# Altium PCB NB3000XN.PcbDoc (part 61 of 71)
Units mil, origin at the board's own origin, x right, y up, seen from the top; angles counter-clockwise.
Board outline 9527.56 x 6929.77 mil, 6 copper layers (Top Layer, GND+SHIELD, MidLayer1, MidLayer2, P2 - 3V3+5V0, Bottom Layer), stack 62.375 mil thick; 832 components, 1027 nets, 4655 pads, 4981 vias.
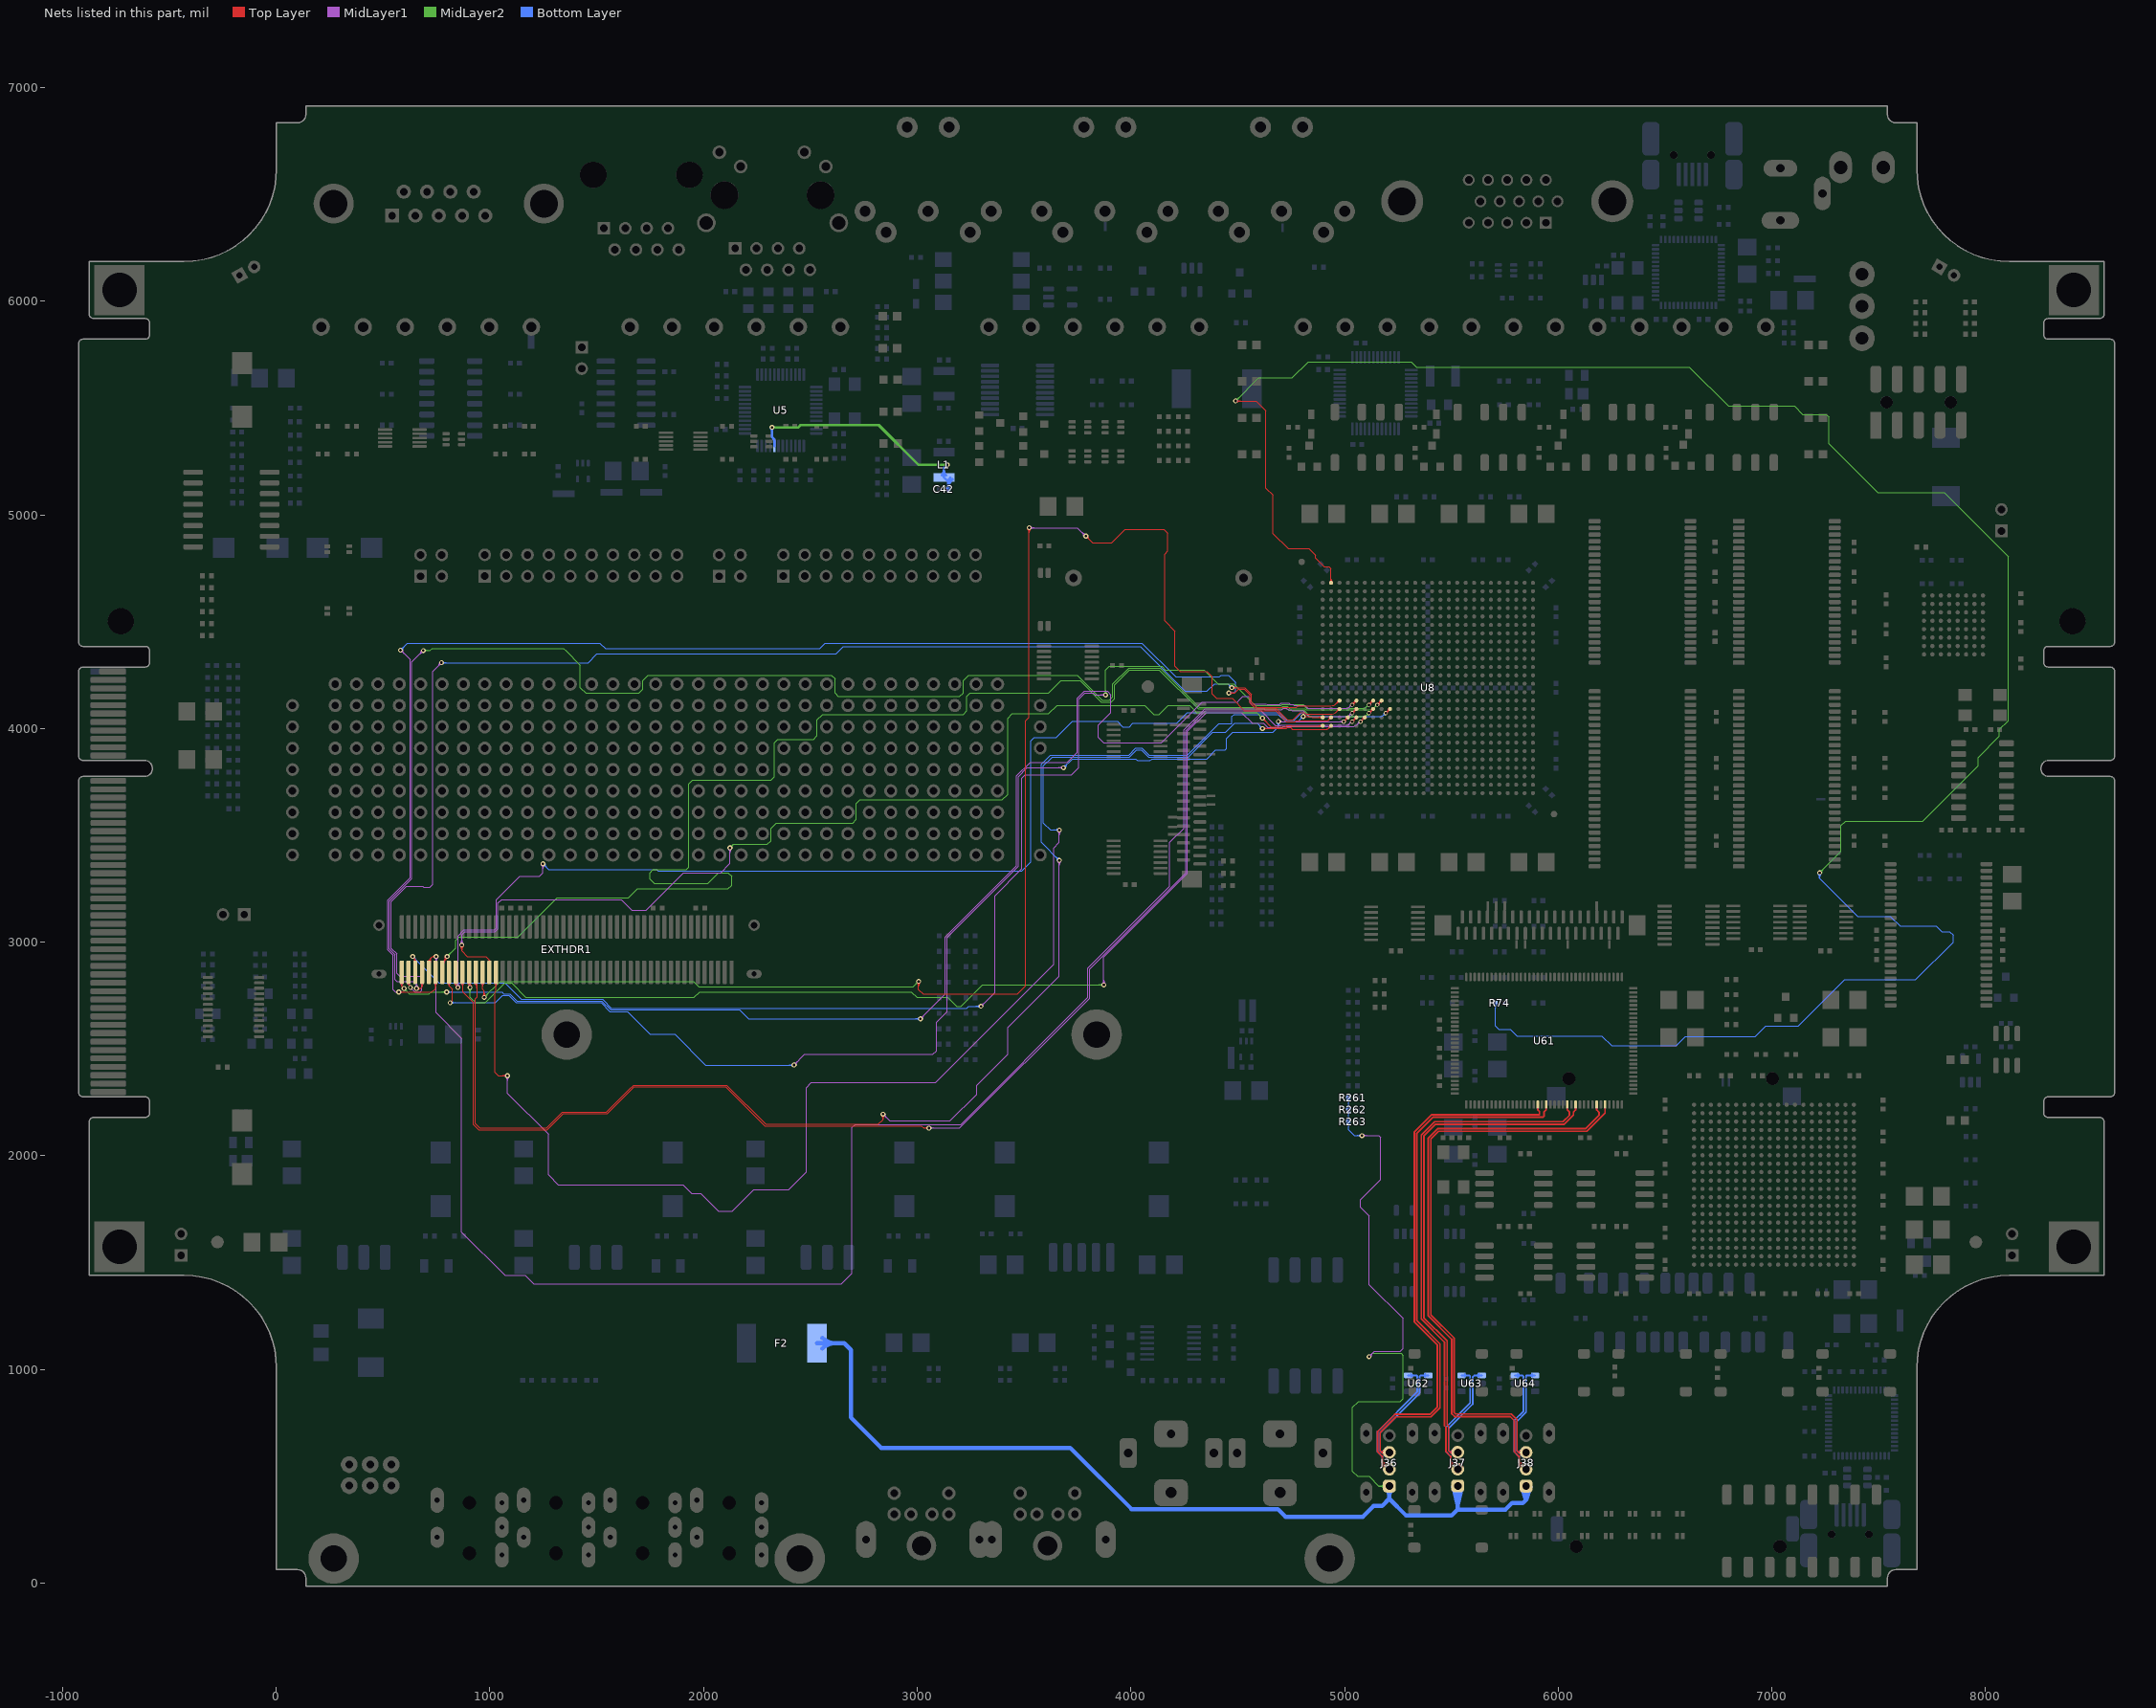
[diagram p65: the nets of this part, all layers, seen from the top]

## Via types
v1: diameter 23, hole 11.81, Top Layer to Bottom Layer, 3672 vias
v2: diameter 26, hole 11.81, Top Layer to Bottom Layer, 461 vias
v3: diameter 19, hole 11.81, Top Layer to Bottom Layer, tented both sides, 396 vias
v4: diameter 23.62, hole 11.81, Top Layer to Bottom Layer, 288 vias
v5: diameter 20, hole 11.81, Top Layer to Bottom Layer, 91 vias
v6: diameter 23, hole 11.81, Top Layer to Bottom Layer, tented both sides, 50 vias
v7: diameter 31, hole 11.81, Top Layer to Bottom Layer, 15 vias
v8: diameter 27.56, hole 11.81, Top Layer to Bottom Layer, tented both sides, 4 vias
v9: diameter 29, hole 11.81, Top Layer to Bottom Layer, 3 vias
v10: diameter 21, hole 11.81, Top Layer to Bottom Layer, 1 vias

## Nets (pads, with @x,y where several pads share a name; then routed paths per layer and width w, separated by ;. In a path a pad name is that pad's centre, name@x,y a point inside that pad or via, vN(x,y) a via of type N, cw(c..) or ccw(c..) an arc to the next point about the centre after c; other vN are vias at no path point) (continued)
PBIO.D35: EXTHDR1.72 U8.V2 | length 7156.9
  Top Layer w4: EXTHDR1.72@1023.3,2808.48 cw(c1009.65,2794.82) 1028.96,2794.82 cw(c1048.27,2794.82) EXTHDR1.72@1034.62,2808.48 ; EXTHDR1.72@1028.96,2814.13 EXTHDR1.72@1028.96,2859.25 1028.96,2770.43 1023.52,2765 1023.52,2391.71 1040.19,2375.04 v1(1081.86,2375.04) ; v1@1075.14,2368.32 ccw(c1058.92,2352.11) 1058.92,2375.04 ccw(c1058.92,2397.98) v1@1075.14,2381.76 ; v1@1077.97,2371.15 ccw(c1068.58,2361.76) 1068.58,2375.04 ccw(c1068.58,2388.32) v1@1077.97,2378.93 ; v1(4616.19,4000.04) 4727.77,4000.04 4732.94,4005.21 4747.44,4005.21 ; v1@4620.08,3996.15 cw(c4629.47,3986.76) 4629.47,4000.04 cw(c4629.47,4013.32) v1@4620.08,4003.93 ; v1@4622.91,3993.32 cw(c4639.13,3977.11) 4639.13,4000.04 cw(c4639.13,4022.98) v1@4622.91,4006.76 ; 4752.65,4000 4747.44,4005.21 ; U8.V2@4929.9,4012.83 cw(c4912.17,4012.83) 4924.71,4000.3 ; U8.V2@4937.24,4005.49 ccw(c4937.24,3987.77) 4924.71,4000.3 ; 4747.44,4005.21 4755.32,3997.33 4860,3997.33 4870,3997.33 4917.53,3997.33 ccw(c4917.53,4007.48) 4924.71,4000.3
  MidLayer1 w4: v1@1075.14,2368.32 cw(c1058.92,2352.11) 1081.86,2352.11 cw(c1104.79,2352.11) v1@1088.57,2368.32 ; v1@1077.97,2371.15 cw(c1068.58,2361.76) 1081.86,2361.76 cw(c1095.14,2361.76) v1@1085.75,2371.15 ; v1(1081.86,2375.04) 1081.86,2293.14 1273.86,2101.14 1273.86,1911.14 1320,1865 1905,1865 1945,1825 1986.71,1825 2070,1741.71 2135,1741.71 2235.29,1842 2398.82,1842 2481.86,1925.04 2481.86,2319.23 2505.13,2342.5 3085.63,2342.5 3108.73,2365.6 ; 3090.98,2347.85 3640,2896.87 3640,3441.52 3665.19,3466.71 v1(3665.19,3525.04) ; v1@3658.47,3518.32 cw(c3642.26,3502.11) 3665.19,3502.11 cw(c3688.13,3502.11) v1@3671.91,3518.32 ; v1@3661.3,3521.15 cw(c3651.91,3511.76) 3665.19,3511.76 cw(c3678.47,3511.76) v1@3669.08,3521.15
  Bottom Layer w4: v1@3658.47,3518.32 ccw(c3642.26,3502.11) 3642.26,3525.04 ccw(c3642.26,3547.98) v1@3658.47,3531.76 ; v1@3661.3,3521.15 ccw(c3651.91,3511.76) 3651.91,3525.04 ccw(c3651.91,3538.32) v1@3661.3,3528.93 ; v1(3665.19,3525.04) 3623.52,3525.04 3590.19,3558.37 3590.19,3825.04 3631.86,3866.71 3993.17,3866.71 4026.5,3900.04 4049.52,3900.04 4082.86,3866.71 4268.17,3866.71 4383.84,3982.37 4410,3982.37 4443.19,3982.37 4485.86,4025.04 4591.19,4025.04 v1(4616.19,4000.04) ; v1@4606.69,4000.04 ccw(c4583.76,4000.04) 4599.97,4016.26 ccw(c4616.19,4032.48) v1@4616.19,4009.54 ; v1@4610.69,4000.04 ccw(c4597.41,4000.04) 4606.8,4009.43 ccw(c4616.19,4018.82) v1@4616.19,4005.54
PBIO.D36: EXTHDR1.74 U8.V1 | length 5688.9
  Top Layer w4: v1@861.81,2979.99 cw(c845.59,2963.77) 868.52,2963.77 cw(c891.46,2963.77) v1@875.24,2979.99 ; v1@864.64,2982.82 cw(c855.25,2973.43) 868.52,2973.43 cw(c881.8,2973.43) v1@872.41,2982.82 ; v1(868.52,2986.71) 868.52,2958.37 893.52,2933.37 981.86,2933.37 997.46,2917.77 ; EXTHDR1.74@993.67,2911.41 ccw(c990.24,2917.77) 997.46,2917.77 ; EXTHDR1.74@997.46,2859.25 997.46,2917.77 ; EXTHDR1.74@1001.26,2911.41 cw(c1004.69,2917.77) 997.46,2917.77 ; v1@4616.19,4039.54 cw(c4616.19,4016.61) 4632.41,4032.82 cw(c4648.63,4049.04) v1@4625.69,4049.04 ; v1@4616.19,4043.54 cw(c4616.19,4030.26) 4625.58,4039.65 cw(c4634.97,4049.04) v1@4621.69,4049.04 ; v1(4616.19,4049.04) 4656.86,4008.37 4724.79,4008.37 4729.63,4013.21 4750.75,4013.21 4751.13,4012.83 4860,4012.83 4870,4012.83 U8.V1@4897.87,4012.83 ; U8.V1@4892.57,4007.53 ccw(c4879.77,3994.73) 4879.77,4012.83 ccw(c4879.77,4030.94) U8.V1@4892.57,4018.14 ; U8.V1@4892.68,4007.64 ccw(c4880.15,3995.11) 4880.15,4012.83 ccw(c4880.15,4030.56) U8.V1@4892.68,4018.03
  MidLayer1 w4: v1@861.81,2993.43 ccw(c845.59,3009.64) 868.52,3009.64 ccw(c891.46,3009.64) v1@875.24,2993.43 ; v1@864.64,2990.6 ccw(c855.25,2999.99) 868.52,2999.99 ccw(c881.8,2999.99) v1@872.41,2990.6 ; v1(868.52,2986.71) 868.52,3035.9 882.34,3049.71 1024.71,3049.71 1038,3063 1038,3183 1055.04,3200.04 1615.19,3200.04 1665.19,3150.04 1731.86,3150.04 1906.82,3325 2080,3325 2123.52,3368.52 v1(2123.52,3441.71) ; v1@2116.81,3434.99 cw(c2100.59,3418.77) 2123.52,3418.77 cw(c2146.46,3418.77) v1@2130.24,3434.99 ; v1@2119.64,3437.82 cw(c2110.25,3428.43) 2123.52,3428.43 cw(c2136.8,3428.43) v1@2127.41,3437.82
  MidLayer2 w4: v1(2123.52,3441.71) 2140.19,3458.37 2298.52,3458.37 2315.19,3475.04 2315.19,3533.37 2340.19,3558.37 2698.52,3558.37 2715.19,3575.04 2715.19,3650.04 2731.86,3666.71 3398.52,3666.71 3423.52,3691.71 3423.52,4048.52 3445,4070 3615.48,4070 3654.19,4108.71 4064.86,4108.71 4106.86,4066.71 4131.86,4066.71 4173.86,4108.71 4275.56,4108.71 4308.9,4075.37 4589.86,4075.37 v1(4616.19,4049.04) ; v1@2123.52,3447.21 ccw(c2123.52,3460.49) 2132.91,3451.1 ccw(c2142.3,3441.71) v1@2129.02,3441.71 ; v1@2123.52,3451.21 ccw(c2123.52,3474.14) 2139.74,3457.93 ccw(c2155.96,3441.71) v1@2133.02,3441.71 ; v1@4606.69,4049.04 ccw(c4583.76,4049.04) 4599.97,4065.26 ccw(c4616.19,4081.48) v1@4616.19,4058.54 ; v1@4610.69,4049.04 ccw(c4597.41,4049.04) 4606.8,4058.43 ccw(c4616.19,4067.82) v1@4616.19,4054.54
PBIO.D37: EXTHDR1.76 U8.U2 | length 7725.5
  Top Layer w4: EXTHDR1.76@960.31,2808.48 cw(c948.53,2796.69) 965.19,2796.69 ; 965.19,2792.94 cw(c987.16,2792.94) EXTHDR1.76@971.62,2808.48 ; 965.19,2802.6 cw(c977.5,2802.6) EXTHDR1.76@968.8,2811.3 ; EXTHDR1.76@965.19,2857.71 965.19,2780 973.52,2771.67 v1(973.52,2741.71) ; v1@966.81,2748.43 ccw(c950.59,2764.64) 973.52,2764.64 ccw(c996.46,2764.64) v1@980.24,2748.43 ; v1@969.64,2745.6 ccw(c960.25,2754.99) 973.52,2754.99 ccw(c986.8,2754.99) v1@977.41,2745.6 ; v1@3000.14,2809.99 cw(c2983.92,2793.77) 3006.86,2793.77 cw(c3029.79,2793.77) v1@3013.57,2809.99 ; v1@3002.97,2812.82 cw(c2993.58,2803.43) 3006.86,2803.43 cw(c3020.14,2803.43) v1@3010.75,2812.82 ; v1(3006.86,2816.71) 3006.86,2778.14 3027.46,2757.54 3469.4,2757.54 3506.86,2795 3506.86,4036.36 3523.86,4053.36 3523.86,4939.86 v4(3524,4940) ; v4@3517.06,4933.06 cw(c3500.66,4916.66) 3523.86,4916.66 ; v4@3519.89,4935.89 cw(c3510.32,4926.32) 3523.86,4926.32 ; 3523.86,4915.97 cw(c3548.03,4915.97) v4@3530.94,4933.06 ; 3523.86,4925.63 cw(c3538.37,4925.63) v4@3528.11,4935.89 ; v4@3789,4891.19 cw(c3789,4867.5) 3805.75,4884.25 cw(c3822.5,4901) v4@3798.81,4901 ; v4@3789,4895.19 cw(c3789,4881.16) 3798.92,4891.08 cw(c3808.84,4901) v4@3794.81,4901 ; v4(3789,4901) 3820,4870 3910.15,4870 3973.52,4933.37 4155,4933.37 4155,4933.04 4173.52,4914.52 4173.52,4832.02 4158,4816.5 4158,4503.86 4206.86,4455 4206.86,4291.71 4231.86,4266.71 4356.86,4266.71 4381.86,4241.71 4381.86,4161.36 4401.84,4141.37 4473.86,4141.37 4531.86,4083.37 4677.94,4083.37 4728.11,4033.21 4769.92,4033.21 4773.41,4036.7 4856.86,4036.7 ; 4855.26,4036.7 4860,4036.7 4870,4036.7 4917.53,4036.7 ; 4917.53,4036.7 ccw(c4917.53,4046.85) 4924.71,4039.67 ; 4917.53,4036.7 ccw(c4917.53,4046.85) 4924.71,4039.67 ; 4924.71,4039.67 ccw(c4912.17,4052.2) 4929.9,4052.2 cw(c4912.17,4052.2) 4924.71,4039.67 ; 4924.71,4039.67 cw(c4937.24,4027.14) 4937.24,4044.86 ccw(c4937.24,4027.14) 4924.71,4039.67
  MidLayer1 w4: v4(3524,4940) 3750,4940 v4(3789,4901) ; v4@3528.11,4935.89 cw(c3538.03,4925.97) 3538.03,4940 cw(c3538.03,4954.03) v4@3528.11,4944.11 ; v4@3530.94,4933.06 cw(c3547.69,4916.31) 3547.69,4940 cw(c3547.69,4963.69) v4@3530.94,4946.94 ; v4@3779.19,4901 ccw(c3755.5,4901) 3772.25,4917.75 ccw(c3789,4934.5) v4@3789,4910.81 ; v4@3783.19,4901 ccw(c3769.16,4901) 3779.08,4910.92 ccw(c3789,4920.84) v4@3789,4906.81
  MidLayer2 w4: v1(973.52,2741.71) 1048.52,2816.71 1920,2816.71 1952.98,2816.71 1977.98,2791.71 2131.86,2791.71 2140,2791.71 2981.86,2791.71 v1(3006.86,2816.71) ; v1@973.52,2747.21 ccw(c973.52,2760.49) 982.91,2751.1 ccw(c992.3,2741.71) v1@979.02,2741.71 ; v1@973.52,2751.21 ccw(c973.52,2774.14) 989.74,2757.93 ccw(c1005.96,2741.71) v1@983.02,2741.71 ; v1@2997.36,2816.71 cw(c2974.42,2816.71) 2990.64,2800.49 cw(c3006.86,2784.27) v1@3006.86,2807.21 ; v1@3001.36,2816.71 cw(c2988.08,2816.71) 2997.47,2807.32 cw(c3006.86,2797.93) v1@3006.86,2811.21
PBIO.D38: EXTHDR1.78 U8.U1 | length 6989.1
  Top Layer w4: EXTHDR1.78@928.81,2808.48 cw(c901.35,2781.01) 940.19,2781.01 ; EXTHDR1.78@931.64,2811.3 cw(c911.01,2790.67) 940.19,2790.67 ; EXTHDR1.78@934.47,2814.13 cw(c920.66,2800.32) 940.19,2800.32 ; EXTHDR1.78@940.19,2858.37 940.19,2745 931.52,2736.33 931.52,2150 951.52,2130 1265,2130 1340,2205 1546.31,2205 1651.23,2309.92 1672.31,2331 2107.69,2331 2290.69,2148 2818,2148 2840,2170 v1(2840,2195) ; v1@2833.28,2188.28 cw(c2817.06,2172.06) 2840,2172.06 cw(c2862.93,2172.06) v1@2846.72,2188.28 ; v1@2836.11,2191.11 cw(c2826.72,2181.72) 2840,2181.72 cw(c2853.28,2181.72) v1@2843.89,2191.11 ; v1(4806.86,4056.71) 4844.19,4056.71 4848.52,4052.37 4848.52,4052.2 4851.26,4052.2 4855.26,4052.2 4860,4052.2 4870,4052.2 U8.U1@4897.87,4052.2 ; U8.U1@4892.57,4046.9 ccw(c4879.77,4034.1) 4879.77,4052.2 ccw(c4879.77,4070.31) U8.U1@4892.57,4057.51 ; 4880.15,4052.2 cw(c4880.15,4034.48) 4892.68,4047.01 ccw(c4880.15,4034.48) 4880.15,4052.2 ; 4880.15,4052.2 ccw(c4880.15,4069.93) 4892.68,4057.4 cw(c4880.15,4069.93) 4880.15,4052.2
  MidLayer1 w4: v1@2840,2185.5 cw(c2840,2162.56) 2856.22,2178.78 cw(c2872.43,2195) v1@2849.5,2195 ; v1@2840,2189.5 cw(c2840,2176.22) 2849.39,2185.61 cw(c2858.78,2195) v1@2845.5,2195 ; v1(2840,2195) v1@2841.74,2193.26 ; v1@2840.19,2191.71 v1@2841.74,2193.26 ; v1@3658.47,3376.66 cw(c3642.26,3360.44) 3665.19,3360.44 cw(c3688.13,3360.44) v1@3671.91,3376.66 ; v1@3661.3,3379.49 cw(c3651.91,3370.1) 3665.19,3370.1 cw(c3678.47,3370.1) v1@3669.08,3379.49 ; v1(3665.19,3383.37) 3665.19,2841.71 3423.52,2600.04 3423.52,2475.04 3279.05,2330.57 3279.05,2288.22 3154.34,2163.5 2871.5,2163.5 v1@2841.74,2193.26
  Bottom Layer w4: v1@3655.69,3383.37 ccw(c3632.76,3383.37) 3648.97,3399.59 ccw(c3665.19,3415.81) v1@3665.19,3392.87 ; v1@3659.69,3383.37 ccw(c3646.41,3383.37) 3655.8,3392.76 ccw(c3665.19,3402.15) v1@3665.19,3388.87 ; v1(3665.19,3383.37) 3581.86,3466.71 3581.86,3833.37 3623.52,3875.04 3990.19,3875.04 4023.52,3908.37 4052.5,3908.37 4086.17,3874.71 4264.86,3874.71 4413.19,4023.04 4471.52,4023.04 4473.52,4025.04 4473.52,4056.37 4483.86,4066.71 4690.19,4066.71 4723.52,4033.37 4783.52,4033.37 v1(4806.86,4056.71) ; v1@4797.36,4056.71 cw(c4774.42,4056.71) 4790.64,4040.49 cw(c4806.86,4024.27) v1@4806.86,4047.21 ; v1@4801.36,4056.71 cw(c4788.08,4056.71) 4797.47,4047.32 cw(c4806.86,4037.93) v1@4806.86,4051.21
PBIO.D39: EXTHDR1.80 U8.U6 | length 5905.1
  Top Layer w4: EXTHDR1.80@897.32,2808.48 cw(c883.66,2794.82) 902.97,2794.82 cw(c922.29,2794.82) EXTHDR1.80@908.63,2808.48 ; v1@900.14,2795.09 ccw(c893.3,2801.94) 902.97,2801.94 ; v1@902.97,2792.26 EXTHDR1.80@902.97,2859.25 ; 902.97,2801.37 ccw(c919.85,2801.37) v1@907.92,2789.44 ; EXTHDR1.80@902.97,2811.03 ccw(c929.51,2811.03) v1@910.75,2792.26 ; EXTHDR1.80@902.97,2820.68 ccw(c939.17,2820.68) v1@913.57,2795.09 ; v3(5075.04,4032.52) U8.U6@5094.72,4052.2 ; U8.U6@5087.22,4052.2 cw(c5069.12,4052.2) 5081.92,4039.4 cw(c5094.72,4026.6) U8.U6@5094.72,4044.7 ; U8.U6@5087.38,4052.2 cw(c5069.66,4052.2) 5082.19,4039.67 cw(c5094.72,4027.14) U8.U6@5094.72,4044.86 ; 5087.84,4045.32 cw(c5075.04,4058.13) 5075.04,4040.02 ccw(c5075.04,4058.13) 5087.84,4045.32 ; 5087.84,4045.32 ccw(c5100.65,4032.52) 5082.54,4032.52 cw(c5100.65,4032.52) 5087.84,4045.32
  MidLayer1 w4: v1@3866.81,2806.76 ccw(c3850.59,2822.98) 3873.52,2822.98 ccw(c3896.46,2822.98) v1@3880.24,2806.76 ; v1@3869.64,2803.93 ccw(c3860.25,2813.32) 3873.52,2813.32 ccw(c3886.8,2813.32) v1@3877.41,2803.93 ; v1(3873.52,2800.04) 3873.52,2930.39 4264.52,3321.39 4264.52,3986.51 4353.05,4075.04 4518.19,4075.04 4568.19,4025.04 4620.52,4025.04 4640.19,4005.37 4710,4005.37 4713.28,4008.66 4860,4008.66 4870,4008.66 4918.62,4008.66 4938.04,4008.66 5012.16,4008.66 ; 4998.23,4008.66 5012.16,4008.66 ; v3@5067.57,4033.17 cw(c5049.53,4034.75) 5061.17,4020.88 ; v3@5074.39,4025.05 ccw(c5072.81,4007.01) 5061.17,4020.88 ; 5012.16,4008.66 5031.66,4008.66 ccw(c5031.66,4050.39) 5061.17,4020.88
  MidLayer2 w4: v1@900.14,2781.66 cw(c883.92,2765.44) 906.86,2765.44 cw(c929.79,2765.44) v1@913.57,2781.66 ; v1@902.97,2784.49 cw(c893.58,2775.1) 906.86,2775.1 cw(c920.14,2775.1) v1@910.75,2784.49 ; v1(906.86,2788.37) 906.86,2743.14 933.29,2716.71 979.52,2716.71 1071.19,2808.37 1101.5,2808.37 1168.17,2741.71 1956.33,2741.71 1982,2767.37 2973.02,2767.37 2998.35,2742.04 3142.96,2742.04 3184.96,2700.04 3205.86,2700.04 3305.86,2800.04 v1(3873.52,2800.04) ; v1@3866.81,2793.32 ccw(c3850.59,2777.11) 3850.59,2800.04 ccw(c3850.59,2822.98) v1@3866.81,2806.76 ; v1@3869.64,2796.15 ccw(c3860.25,2786.76) 3860.25,2800.04 ccw(c3860.25,2813.32) v1@3869.64,2803.93
PBIO.D40: EXTHDR1.82 U8.U5 | length 6640.7
  Top Layer w4: EXTHDR1.82@865.82,2808.48 cw(c847.23,2789.88) 873.52,2789.88 ; EXTHDR1.82@868.65,2811.3 cw(c856.88,2799.54) 873.52,2799.54 ; 873.52,2799.76 cw(c885.85,2799.76) EXTHDR1.82@877.14,2808.48 ; EXTHDR1.82@873.52,2859.25 873.52,2766.48 923.52,2716.48 923.52,2146.69 948.21,2122 1268.31,2122 1343.31,2197 1549.63,2197 1675.63,2323 2104.37,2323 2287.37,2140 3020,2140 3030,2130 v1(3055,2130) ; v1@3048.28,2123.28 ccw(c3032.06,2107.06) 3032.06,2130 ccw(c3032.06,2152.93) v1@3048.28,2136.72 ; v1@3051.11,2126.11 ccw(c3041.72,2116.72) 3041.72,2130 ccw(c3041.72,2143.28) v1@3051.11,2133.89 ; v3(5035.67,4032.52) U8.U5@5055.35,4052.2 ; U8.U5@5047.85,4052.2 cw(c5029.75,4052.2) 5042.55,4039.4 cw(c5055.35,4026.6) U8.U5@5055.35,4044.7 ; U8.U5@5048.01,4052.2 cw(c5030.29,4052.2) 5042.82,4039.67 cw(c5055.35,4027.14) U8.U5@5055.35,4044.86 ; 5048.47,4045.32 cw(c5035.67,4058.13) 5035.67,4040.02 ccw(c5035.67,4058.13) 5048.47,4045.32 ; 5048.47,4045.32 ccw(c5061.28,4032.52) 5043.17,4032.52 cw(c5061.28,4032.52) 5048.47,4045.32
  MidLayer1 w4: v1(3055,2130) 3198.13,2130 3806.86,2738.73 3806.86,2875.04 4234.16,3302.35 4256.52,3324.71 4256.52,3989.82 4350.07,4083.37 4608.52,4083.37 4676.86,4015.04 4700,4015.04 4701.97,4017.01 4860,4017.01 4870,4017.01 4918.62,4017.01 5012.16,4017.01 ccw(c5012.16,4031.06) 5022.09,4021.13 ; v1@3058.89,2126.11 cw(c3068.28,2116.72) 3068.28,2130 cw(c3068.28,2143.28) v1@3058.89,2133.89 ; v1@3061.72,2123.28 cw(c3077.93,2107.06) 3077.93,2130 cw(c3077.93,2152.93) v1@3061.72,2136.72 ; v3@5028.2,4033.17 cw(c5010.16,4034.75) 5021.8,4020.88 cw(c5033.44,4007.01) v3@5035.02,4025.05
PBIO.D41: EXTHDR1.84 U8.T9 | length 5958.9
  Top Layer w4: EXTHDR1.84@835.33,2807.62 cw(c828.87,2798.58) 839.98,2798.58 ; EXTHDR1.84@839.98,2859.25 839.98,2798.58 ; EXTHDR1.84@844.63,2807.62 ccw(c851.09,2798.58) 839.98,2798.58 ; v1(850.52,2788.04) 839.98,2798.58 ; v3(5193.15,4071.89) U8.T9@5212.83,4091.57 ; U8.T9@5205.33,4091.57 cw(c5187.23,4091.57) 5200.03,4078.77 cw(c5212.83,4065.97) U8.T9@5212.83,4084.07 ; U8.T9@5205.49,4091.57 cw(c5187.77,4091.57) 5200.3,4079.04 cw(c5212.83,4066.51) U8.T9@5212.83,4084.23 ; 5205.95,4084.69 cw(c5193.15,4097.5) 5193.15,4079.39 ccw(c5193.15,4097.5) 5205.95,4084.69 ; 5205.95,4084.69 ccw(c5218.76,4071.89) 5200.65,4071.89 cw(c5218.76,4071.89) 5205.95,4084.69
  MidLayer1 w4: v1@843.81,2794.76 ccw(c827.59,2810.98) 850.52,2810.98 ccw(c873.46,2810.98) v1@857.24,2794.76 ; v1@846.64,2791.93 ccw(c837.25,2801.32) 850.52,2801.32 ccw(c863.8,2801.32) v1@854.41,2791.93 ; v1(850.52,2788.04) 850.52,3029.21 879.02,3057.71 1021.39,3057.71 1030,3066.31 1030,3198.18 1088.77,3256.96 1140.19,3308.37 1231.86,3308.37 1248.52,3325.04 v1(1248.52,3366.71) ; v1@1241.81,3359.99 cw(c1225.59,3343.77) 1248.52,3343.77 cw(c1271.46,3343.77) v1@1255.24,3359.99 ; v1@1244.64,3362.82 cw(c1235.25,3353.43) 1248.52,3353.43 cw(c1261.8,3353.43) v1@1252.41,3362.82
  Bottom Layer w4: v1@1248.52,3357.21 cw(c1248.52,3334.27) 1264.74,3350.49 cw(c1280.96,3366.71) v1@1258.02,3366.71 ; v1@1248.52,3361.21 cw(c1248.52,3347.93) 1257.91,3357.32 cw(c1267.3,3366.71) v1@1254.02,3366.71 ; v1(1248.52,3366.71) 1274.19,3341.04 1780.15,3341.04 1787.82,3333.37 3490.19,3333.37 3531.86,3375.04 3531.86,3941.71 3548.52,3958.37 3651.51,3958.37 3726.84,4033.71 3936.88,4033.71 3962.21,4008.37 3993.17,4008.37 4009.84,4025.04 4215.19,4025.04 4265.19,4075.04 4693.17,4075.04 4726.5,4041.71 4765.19,4041.71 4798.52,4075.04 4815,4075.04 4833.66,4056.38 4860,4056.38 4870,4056.38 5076.1,4056.38 5169.64,4056.38 ccw(c5169.64,4070.43) 5179.57,4060.5 ; v3@5185.68,4072.54 cw(c5167.64,4074.12) 5179.28,4060.25 cw(c5190.92,4046.38) v3@5192.5,4064.42
PBIO.D42: EXTHDR1.86 U8.U4 | length 6374
  Top Layer w4: EXTHDR1.86@803.22,2808.11 cw(c793.09,2796.51) 808.49,2796.51 ; EXTHDR1.86@808.49,2859.25 808.49,2796.51 ; EXTHDR1.86@813.75,2808.11 ccw(c823.89,2796.51) 808.49,2796.51 ; v1(814.19,2716.71) 825,2727.52 825,2780 808.49,2796.51 ; v3(4996.3,4032.52) U8.U4@5015.98,4052.2 ; U8.U4@5008.48,4052.2 cw(c4990.38,4052.2) 5003.18,4039.4 cw(c5015.98,4026.6) U8.U4@5015.98,4044.7 ; U8.U4@5008.64,4052.2 cw(c4990.92,4052.2) 5003.45,4039.67 cw(c5015.98,4027.14) U8.U4@5015.98,4044.86 ; 5009.1,4045.32 cw(c4996.3,4058.13) 4996.3,4040.02 ccw(c4996.3,4058.13) 5009.1,4045.32 ; 5009.1,4045.32 ccw(c5021.91,4032.52) 5003.8,4032.52 cw(c5021.91,4032.52) 5009.1,4045.32
  MidLayer1 w4: v1(2423.52,2425.04) 2473.52,2475.04 3073.52,2475.04 3090.19,2491.71 3090.19,2625.04 3140.19,2675.04 3140.19,3022.06 3473.52,3355.39 3473.52,3775.04 3515.19,3816.71 v1(3684.86,3816.71) ; v1@2423.52,2430.54 ccw(c2423.52,2443.82) 2432.91,2434.43 ccw(c2442.3,2425.04) v1@2429.02,2425.04 ; v1@2423.52,2434.54 ccw(c2423.52,2457.48) 2439.74,2441.26 ccw(c2455.96,2425.04) v1@2433.02,2425.04 ; v1@3678.14,3809.99 ccw(c3661.92,3793.77) 3661.92,3816.71 ccw(c3661.92,3839.64) v1@3678.14,3823.43 ; v1@3680.97,3812.82 ccw(c3671.58,3803.43) 3671.58,3816.71 ccw(c3671.58,3829.99) v1@3680.97,3820.6 ; v1(4690.19,4033.37) 4692.36,4031.21 4820,4031.21 4821.31,4032.52 4860,4032.52 4870,4032.52 4918.62,4032.52 v3(4996.3,4032.52) ; v1@4694.08,4037.26 ccw(c4708.7,4051.88) 4708.7,4031.21 ; v1@4696.91,4026.66 cw(c4707.89,4015.67) 4707.89,4031.21 ; v1@4696.91,4040.09 ccw(c4718.36,4061.54) 4718.36,4031.21 ; v3@4991.11,4027.33 ccw(c4978.57,4014.79) 4978.57,4032.52 ccw(c4978.57,4050.25) v3@4991.11,4037.71 ; 4978.19,4032.52 ccw(c4978.19,4050.63) 4991,4037.82 cw(c4978.19,4050.63) 4978.19,4032.52 ; 4978.19,4032.52 cw(c4978.19,4014.41) 4991,4027.22 ccw(c4978.19,4014.41) 4978.19,4032.52
  Bottom Layer w4: v1(814.19,2716.71) 1025.96,2716.71 1059.63,2750.37 1089.6,2750.37 1103.68,2736.3 ; v1@818.08,2712.82 cw(c827.47,2703.43) 827.47,2716.71 cw(c827.47,2729.99) v1@818.08,2720.6 ; v1@820.91,2709.99 cw(c837.13,2693.77) 837.13,2716.71 cw(c837.13,2739.64) v1@820.91,2723.43 ; 1103.63,2736.25 1122.5,2717.37 1520.23,2717.37 1561.9,2675.71 1644.29,2675.71 1750,2570 1865,2570 2009.96,2425.04 v1(2423.52,2425.04) ; v1@2416.81,2418.32 ccw(c2400.59,2402.11) 2400.59,2425.04 ccw(c2400.59,2447.98) v1@2416.81,2431.76 ; v1@2419.64,2421.15 ccw(c2410.25,2411.76) 2410.25,2425.04 ccw(c2410.25,2438.32) v1@2419.64,2428.93 ; v1(3684.86,3816.71) 3726.52,3858.37 4023.52,3858.37 4031.86,3850.04 4090.19,3850.04 4098.52,3858.37 4356.86,3858.37 4397.52,3899.04 4440.19,3899.04 4448.52,3907.37 4448.52,3953.02 4477.88,3982.37 4665.19,3982.37 4690.19,4007.37 v1(4690.19,4033.37) ; v1@3684.86,3822.21 ccw(c3684.86,3835.49) 3694.25,3826.1 ccw(c3703.64,3816.71) v1@3690.36,3816.71 ; v1@3684.86,3826.21 ccw(c3684.86,3849.14) 3701.07,3832.93 ccw(c3717.29,3816.71) v1@3694.36,3816.71 ; v1@4683.47,4026.66 cw(c4667.26,4010.44) 4690.19,4010.44 cw(c4713.13,4010.44) v1@4696.91,4026.66 ; v1@4686.3,4029.49 cw(c4676.91,4020.1) 4690.19,4020.1 cw(c4703.47,4020.1) v1@4694.08,4029.49
PBIO.D43: EXTHDR1.88 U8.T7 | length 6778.2
  Top Layer w4: EXTHDR1.88@776.99,2859.25 776.99,2902.17 804.02,2929.21 808.19,2933.37 v1(799.86,2933.37) ; EXTHDR1.88@776.99,2908.37 ccw(c776.99,2923.32) 787.56,2912.75 ; EXTHDR1.88@776.99,2912.37 ccw(c776.99,2936.98) 794.39,2919.58 ; EXTHDR1.88@781.16,2906.34 ccw(c758.41,2929.09) v1@790.41,2932.4 ; EXTHDR1.88@784.99,2904.37 cw(c799.01,2904.37) 789.1,2914.28 ; 787.1,2912.28 ccw(c769.18,2930.2) v1@794.39,2932.81 ; 793.04,2918.23 ccw(c779.95,2931.31) v1@798.37,2933.22 ; v3(5114.41,4071.89) U8.T7@5134.09,4091.57 ; U8.T7@5126.59,4091.57 cw(c5108.49,4091.57) 5121.29,4078.77 cw(c5134.09,4065.97) U8.T7@5134.09,4084.07 ; U8.T7@5126.75,4091.57 cw(c5109.03,4091.57) 5121.56,4079.04 cw(c5134.09,4066.51) U8.T7@5134.09,4084.23 ; 5127.21,4084.69 cw(c5114.41,4097.5) 5114.41,4079.39 ccw(c5114.41,4097.5) 5127.21,4084.69 ; 5127.21,4084.69 ccw(c5140.02,4071.89) 5121.91,4071.89 cw(c5140.02,4071.89) 5127.21,4084.69
  MidLayer2 w4: v1(799.86,2933.37) 840.19,2973.71 840.19,3008.37 856.86,3025.04 1131.86,3025.04 1305.18,3198.37 1314.86,3208.04 1649.35,3208.04 1691.35,3250.04 2115.19,3250.04 2131.86,3266.71 2131.86,3308.37 2115.19,3325.04 2070,3325.04 2020,3275.04 1768.86,3275.04 1748.52,3295.37 1748.52,3325.04 1763.48,3340 1920,3340 1931.86,3351.86 1931.86,3741.71 1948.52,3758.37 2315.19,3758.37 2331.86,3775.04 2331.86,3933.37 2348.52,3950.04 2515.19,3950.04 2531.86,3966.71 2531.86,4041.71 2556.86,4066.71 3215.19,4066.71 3231.86,4083.37 3231.86,4150.04 3248.52,4166.71 3615.19,4166.71 3673.52,4225.04 3762.21,4225.04 3862.21,4125.04 3907.86,4125.04 3923.52,4140.71 3923.52,4205.39 3993.13,4275 4080,4275 4131.86,4275.04 4315.19,4091.71 4709.71,4091.71 4713.92,4095.92 4728.67,4095.92 4739.55,4085.04 4810,4085.04 4838.66,4056.38 4860,4056.38 4870,4056.38 4997.36,4056.38 5090.9,4056.38 ccw(c5090.9,4070.43) 5100.83,4060.5 ; v1@799.86,2938.87 ccw(c799.86,2952.15) 809.25,2942.76 ccw(c818.64,2933.37) v1@805.36,2933.37 ; v1@799.86,2942.87 ccw(c799.86,2965.81) 816.07,2949.59 ccw(c832.29,2933.37) v1@809.36,2933.37 ; v3@5106.94,4072.54 cw(c5088.9,4074.12) 5100.54,4060.25 cw(c5112.18,4046.38) v3@5113.76,4064.42
PBIO.D44: EXTHDR1.90 U8.T3 | length 7061.7
  Top Layer w4: v1@577.41,2770.6 ccw(c588.81,2782) 588.81,2765.87 ; v1@580.24,2759.99 cw(c594.45,2745.78) 594.45,2765.87 ; v1@580.24,2773.43 ccw(c598.47,2791.65) 598.47,2765.87 ; EXTHDR1.90@739.84,2808.48 cw(c726.18,2794.82) 745.49,2794.82 cw(c764.81,2794.82) EXTHDR1.90@751.15,2808.48 ; EXTHDR1.90@745.49,2859.25 745.49,2781.97 729.4,2765.87 v1@581.02,2765.87 ; v1(4458.52,4166.71) 4486.71,4166.71 4503.71,4183.71 4530.88,4183.71 4557.19,4157.39 4557.19,4120.04 4585.52,4091.71 4650,4091.71 ; v1@4462.41,4162.82 cw(c4471.8,4153.43) 4471.8,4166.71 cw(c4471.8,4179.99) v1@4462.41,4170.6 ; v1@4465.24,4159.99 cw(c4481.46,4143.77) 4481.46,4166.71 cw(c4481.46,4189.64) v1@4465.24,4173.43 ; 4676.54,4091.71 4650,4091.71 ; 4855.26,4067.71 4860,4067.71 ; U8.T3@4969.27,4091.57 cw(c4951.55,4091.57) 4964.08,4079.04 ; U8.T3@4976.61,4084.23 ccw(c4976.61,4066.51) 4964.08,4079.04 ; v1@581.02,2765.87 574.36,2765.87 v1(573.52,2766.71) 580.19,2766.71 v1@581.02,2765.87 ; 4650,4091.71 4680.92,4091.71 4731.42,4041.21 4759.09,4041.21 4792.09,4074.21 4814.11,4074.21 4820.46,4067.85 ; 4820.46,4067.85 4820.46,4067.71 4820.6,4067.71 ; 4820.46,4067.85 4820.6,4067.71 ; 4820.6,4067.71 4856.86,4067.71 4860,4067.71 ; 4860,4067.71 4870,4067.71 ; 4870,4067.71 4896.53,4067.71 ; 4870,4067.71 4896.53,4067.71 ; 4896.53,4067.71 4936.73,4067.71 ccw(c4936.73,4106.39) 4964.08,4079.04
  MidLayer1 w4: v1(573.52,2766.71) 558.29,2766.71 547.86,2777.14 547.86,2938.48 521.61,2964.73 521.61,3196.35 627,3301.75 627,4323 v1@580,4370 ; v1@581.86,4357.21 cw(c581.86,4330.81) 600.52,4349.48 ; v1@581.86,4361.21 cw(c581.86,4344.47) 593.7,4356.3 ; v1@591.36,4366.71 ccw(c610.83,4366.71) 597.06,4352.94
  Bottom Layer w4: v1(581.86,4366.71) 615.19,4400.04 1515,4400.04 1540.67,4374.37 2544.33,4374.37 2570,4400.04 4051.54,4400.04 4209.88,4241.71 4415.19,4241.71 4423.52,4250.04 4456.86,4250.04 4490.19,4216.71 4490.19,4175.04 4481.86,4166.71 v1(4458.52,4166.71) ; v1@581.86,4372.21 ccw(c581.86,4385.49) 591.25,4376.1 ccw(c600.64,4366.71) v1@587.36,4366.71 ; v1@581.86,4376.21 ccw(c581.86,4399.14) 598.07,4382.93 ccw(c614.29,4366.71) v1@591.36,4366.71 ; v1@4462.41,4162.82 cw(c4471.8,4153.43) 4471.8,4166.71 cw(c4471.8,4179.99) v1@4462.41,4170.6 ; v1@4465.24,4159.99 cw(c4481.46,4143.77) 4481.46,4166.71 cw(c4481.46,4189.64) v1@4465.24,4173.43
PBIO.D45: EXTHDR1.92 U8.T5 | length 8027
  Top Layer w4: EXTHDR1.92@710.18,2903.17 cw(c720.88,2906.54) 712.95,2914.47 ; EXTHDR1.92@711.44,2911.95 ccw(c710.23,2915.51) 714,2915.51 ; EXTHDR1.92@714,2859.25 714,2915.52 ; EXTHDR1.92@714,2904.37 cw(c727.97,2908.77) 717.61,2919.13 ; EXTHDR1.92@716.56,2911.95 cw(c717.76,2915.51) 714,2915.51 ; EXTHDR1.92@717.81,2905.57 cw(c735.06,2911) 722.28,2923.79 ; EXTHDR1.92@721.63,2906.77 cw(c742.16,2913.24) 726.94,2928.46 ; v1@740.35,2928.53 ccw(c731.86,2923.51) 731.86,2933.37 ; v1@740.35,2938.22 cw(c731.86,2943.24) 731.86,2933.37 ; v1(748.52,2933.37) 731.86,2933.37 ; v3(5035.67,4071.89) U8.T5@5055.35,4091.57 ; U8.T5@5047.85,4091.57 cw(c5029.75,4091.57) 5042.55,4078.77 cw(c5055.35,4065.97) U8.T5@5055.35,4084.07 ; U8.T5@5048.01,4091.57 cw(c5030.29,4091.57) 5042.82,4079.04 cw(c5055.35,4066.51) U8.T5@5055.35,4084.23 ; 714,2915.52 726.94,2928.46 ; 726.94,2928.46 731.86,2933.37 ; 5048.47,4084.69 cw(c5035.67,4097.5) 5035.67,4079.39 ccw(c5035.67,4097.5) 5048.47,4084.69 ; 5048.47,4084.69 ccw(c5061.28,4071.89) 5043.17,4071.89 cw(c5061.28,4071.89) 5048.47,4084.69
  MidLayer1 w4: v1@741.81,2926.66 cw(c725.59,2910.44) 748.52,2910.44 cw(c771.46,2910.44) v1@755.24,2926.66 ; v1@744.64,2929.49 cw(c735.25,2920.1) 748.52,2920.1 cw(c761.8,2920.1) v1@752.41,2929.49 ; v1(748.52,2933.37) 748.52,2669.64 868,2550.16 868,1643.06 1070.56,1440.5 1165.56,1440.5 1206.02,1400.04 2645,1400.04 2695,1450.04 2695,2132.5 2710,2147.5 3204.32,2147.5 3798.86,2742.04 3798.86,2878.36 3850.43,2929.93 4181.86,3261.36 4181.86,3466.71 4248.52,3533.37 4248.52,3993.14 4347.09,4091.71 4623.52,4091.71 4627.52,4087.71 4705.71,4087.71 4713.92,4095.92 4728.67,4095.92 4736.88,4087.71 4749.53,4087.71 4753.86,4083.37 4806.86,4083.37 4833.85,4056.38 4860,4056.38 4870,4056.38 4918.62,4056.38 5012.16,4056.38 ccw(c5012.16,4070.43) 5022.09,4060.5 ; v3@5028.2,4072.54 cw(c5010.16,4074.12) 5021.8,4060.25 cw(c5033.44,4046.38) v3@5035.02,4064.42
PBIO.D46: EXTHDR1.94 U8.R8 | length 7292.9
  Top Layer w4: v1(656.86,2783.37) 674.5,2783.37 ; v1@664.79,2778.14 cw(c674.5,2771.74) 674.5,2783.37 ; v1@664.79,2788.6 ccw(c674.5,2795.01) 674.5,2783.37 ; EXTHDR1.94@676.85,2808.48 cw(c663.19,2794.82) 682.5,2794.82 cw(c701.82,2794.82) EXTHDR1.94@688.16,2808.48 ; EXTHDR1.94@682.5,2859.25 682.5,2791.37 674.5,2783.37 ; v3(5153.78,4111.26) U8.R8@5173.46,4130.94 ; U8.R8@5165.96,4130.94 cw(c5147.86,4130.94) 5160.66,4118.14 cw(c5173.46,4105.34) U8.R8@5173.46,4123.44 ; U8.R8@5166.12,4130.94 cw(c5148.4,4130.94) 5160.93,4118.41 cw(c5173.46,4105.88) U8.R8@5173.46,4123.6 ; 5166.58,4124.06 cw(c5153.78,4136.87) 5153.78,4118.76 ccw(c5153.78,4136.87) 5166.58,4124.06 ; 5166.58,4124.06 ccw(c5179.39,4111.26) 5161.28,4111.26 cw(c5179.39,4111.26) 5166.58,4124.06
  MidLayer1 w4: v1@650.14,2790.09 ccw(c633.92,2806.31) 656.86,2806.31 ccw(c679.79,2806.31) v1@663.57,2790.09 ; v1@652.97,2787.26 ccw(c643.58,2796.65) 656.86,2796.65 ccw(c670.14,2796.65) v1@660.75,2787.26 ; v1(656.86,2783.37) 656.86,2808.14 650,2815 565,2815 555.86,2824.14 555.86,2941.8 529.61,2968.04 529.61,3193.04 635,3298.43 635,4311.52 v1(688.52,4365.04) ; v1@679.02,4365.04 cw(c656.09,4365.04) 672.31,4348.82 cw(c688.52,4332.61) v1@688.52,4355.54 ; v1@683.02,4365.04 cw(c669.75,4365.04) 679.14,4355.65 cw(c688.52,4346.26) v1@688.52,4359.54
  MidLayer2 w4: v1(688.52,4365.04) 720,4365.04 730.33,4375.37 1344.67,4375.37 1355,4365.04 1355.54,4365.04 1423.52,4297.06 1423.52,4191.71 1448.52,4166.71 1698.52,4166.71 1715.19,4183.37 1715.19,4225.04 1740.19,4250.04 2598.52,4250.04 2615.19,4233.37 2615.19,4165.71 2630.52,4150.37 2630.52,4150 2655,4150 3198.52,4150.04 3215.19,4166.71 3215.19,4225.04 3240.19,4250.04 3748.52,4250.04 3865.19,4133.37 3899.86,4133.37 3915.19,4148.71 3915.19,4208.37 3990.19,4283.37 4137.52,4283.37 4320.86,4100.04 4706.73,4100.04 4710.61,4103.92 4731.99,4103.92 4742.86,4093.04 4813.31,4093.04 4818.96,4087.4 4860,4087.4 4870,4087.4 4997.36,4087.4 5016.78,4087.4 5090.9,4087.4 5110.4,4087.4 ccw(c5110.4,4129.13) 5139.91,4099.62 ; v1@692.41,4361.15 cw(c701.8,4351.76) 701.8,4365.04 cw(c701.8,4378.32) v1@692.41,4368.93 ; v1@695.24,4358.32 cw(c711.46,4342.11) 711.46,4365.04 cw(c711.46,4387.98) v1@695.24,4371.76 ; v3@5146.31,4111.91 cw(c5128.27,4113.49) 5139.91,4099.62 ; v3@5153.13,4103.79 ccw(c5151.55,4085.75) 5139.91,4099.62
PBIO.D47: EXTHDR1.96 U8.R7 | length 6631.3
  Top Layer w4: v1(638.52,2933.37) 648.52,2923.37 ; EXTHDR1.96@645.35,2910.03 ccw(c637.68,2917.69) 648.52,2917.69 ; EXTHDR1.96@648.52,2883.37 648.52,2923.37 ; 648.52,2916.12 ccw(c658.42,2916.12) EXTHDR1.96@653.14,2907.75 ; EXTHDR1.96@655.27,2911.13 cw(c663,2923.37) 648.52,2923.37 ; v3(5114.41,4111.26) U8.R7@5134.09,4130.94 ; U8.R7@5126.59,4130.94 cw(c5108.49,4130.94) 5121.29,4118.14 cw(c5134.09,4105.34) U8.R7@5134.09,4123.44 ; U8.R7@5126.75,4130.94 cw(c5109.03,4130.94) 5121.56,4118.41 cw(c5134.09,4105.88) U8.R7@5134.09,4123.6 ; 5127.21,4124.06 cw(c5114.41,4136.87) 5114.41,4118.76 ccw(c5114.41,4136.87) 5127.21,4124.06 ; 5127.21,4124.06 ccw(c5140.02,4111.26) 5121.91,4111.26 cw(c5140.02,4111.26) 5127.21,4124.06
  MidLayer1 w4: v1(3298.52,2700.04) 3363,2764.52 3363,3218 3489.52,3344.52 3489.52,3768.41 3504.49,3783.37 3723.37,3783.37 3756.19,3816.19 3756.19,4138.06 3785.17,4167.04 3822.96,4167.04 3832.96,4157.04 v1(3881.86,4157.04) ; v1@3298.52,2705.54 ccw(c3298.52,2718.82) 3307.91,2709.43 ccw(c3317.3,2700.04) v1@3304.02,2700.04 ; v1@3298.52,2709.54 ccw(c3298.52,2732.48) 3314.74,2716.26 ccw(c3330.96,2700.04) v1@3308.02,2700.04 ; v1@3875.14,4150.32 ccw(c3858.92,4134.11) 3858.92,4157.04 ccw(c3858.92,4179.98) v1@3875.14,4163.76 ; v1@3877.97,4153.15 ccw(c3868.58,4143.76) 3868.58,4157.04 ccw(c3868.58,4170.32) v1@3877.97,4160.93
  MidLayer2 w4: v1@3875.14,4163.76 ccw(c3858.92,4179.98) 3881.86,4179.98 ccw(c3904.79,4179.98) v1@3888.57,4163.76 ; v1@3877.97,4160.93 ccw(c3868.58,4170.32) 3881.86,4170.32 ccw(c3895.14,4170.32) v1@3885.75,4160.93 ; v1(3881.86,4157.04) 3881.86,4275.04 3898.52,4291.71 4144.86,4291.71 4161.52,4275.04 4342.19,4275.04 4407.86,4209.37 4481.86,4209.37 4582.86,4108.37 4703.75,4108.37 4707.29,4111.92 4805.75,4111.92 4821.92,4095.75 4860,4095.75 4870,4095.75 4997.36,4095.75 5090.9,4095.75 ccw(c5090.9,4109.8) 5100.83,4099.87 ; v3@5106.94,4111.91 cw(c5088.9,4113.49) 5100.54,4099.62 cw(c5112.18,4085.75) v3@5113.76,4103.79
  Bottom Layer w4: v1@638.52,2923.87 cw(c638.52,2900.94) 654.74,2917.16 cw(c670.96,2933.37) v1@648.02,2933.37 ; v1@638.52,2927.87 cw(c638.52,2914.6) 647.91,2923.99 cw(c657.3,2933.37) v1@644.02,2933.37 ; v1(638.52,2933.37) 761.9,2810 1070,2810 1146.63,2733.37 1526.86,2733.37 1568.52,2691.71 3231.86,2691.71 3240.19,2700.04 v1(3298.52,2700.04) ; v1@3291.81,2693.32 ccw(c3275.59,2677.11) 3275.59,2700.04 ccw(c3275.59,2722.98) v1@3291.81,2706.76 ; v1@3294.64,2696.15 ccw(c3285.25,2686.76) 3285.25,2700.04 ccw(c3285.25,2713.32) v1@3294.64,2703.93
PBIO.D48: EXTHDR1.98 U8.R3 | length 6674.9
  Top Layer w4: EXTHDR1.98@616.39,2806.77 cw(c614.39,2802.06) 619.51,2802.06 ; EXTHDR1.98@619.51,2859.25 619.51,2802.05 ; EXTHDR1.98@622.63,2806.77 ccw(c624.63,2802.06) 619.51,2802.06 ; v1(627.86,2788.37) 627.86,2793.71 619.51,2802.05 ; v1(4472.52,4191.71) 4534.19,4191.71 4565.19,4160.71 4565.19,4123.37 4588.86,4099.71 4775.62,4099.71 4783,4107.08 4855.26,4107.08 4860,4107.08 4870,4107.08 4936.73,4107.08 ccw(c4936.73,4145.76) 4964.08,4118.41 ; v1@4476.41,4187.82 cw(c4485.8,4178.43) 4485.8,4191.71 cw(c4485.8,4204.99) v1@4476.41,4195.6 ; v1@4479.24,4184.99 cw(c4495.46,4168.77) 4495.46,4191.71 cw(c4495.46,4214.64) v1@4479.24,4198.43 ; U8.R3@4969.27,4130.94 cw(c4951.55,4130.94) 4964.08,4118.41 ; U8.R3@4976.61,4123.6 ccw(c4976.61,4105.88) 4964.08,4118.41
  MidLayer1 w4: 549.88,3202 578,3230.12 ; v1(627.86,2788.37) 627.86,2787.63 649.61,2765.87 672.69,2765.87 673.52,2766.71 ; v1@764.02,4308.37 cw(c741.09,4308.37) 757.31,4292.16 cw(c773.52,4275.94) v1@773.52,4298.87 ; v1@768.02,4308.37 cw(c754.75,4308.37) 764.14,4298.99 cw(c773.52,4289.6) v1@773.52,4302.87 ; v1(773.52,4308.37) 731.86,4266.71 731.86,3270 719.4,3257.54 691.28,3257.54 686.32,3262.5 610.38,3262.5 578,3230.12 ; 578,3230.12 537.61,3189.73 537.61,2971.36 563.86,2945.11 563.86,2855 577.4,2841.46 673.54,2841.46 681.86,2833.14 681.86,2775.04 ; 673.52,2766.71 681.86,2775.04 ; 673.52,2766.71 681.86,2775.04
  Bottom Layer w4: v1(773.52,4308.37) 1460,4308.37 1502,4350.37 1632.19,4350.37 1685,4350.37 2620.37,4350.37 2654.04,4384.04 4044.92,4384.04 4253.92,4175.04 4356.86,4175.04 4391.19,4209.37 4454.86,4209.37 v1(4472.52,4191.71) ; v1@777.41,4304.49 cw(c786.8,4295.1) 786.8,4308.37 cw(c786.8,4321.65) v1@777.41,4312.26 ; v1@780.24,4301.66 cw(c796.46,4285.44) 796.46,4308.37 cw(c796.46,4331.31) v1@780.24,4315.09 ; v1@4463.02,4191.71 ccw(c4440.09,4191.71) 4456.31,4207.93 ccw(c4472.52,4224.14) v1@4472.52,4201.21 ; v1@4467.02,4191.71 ccw(c4453.75,4191.71) 4463.14,4201.1 ccw(c4472.52,4210.49) v1@4472.52,4197.21
PBIO.D49: EXTHDR1.100 U8.R5 | length 6670
  Top Layer w4: EXTHDR1.100@582.36,2808.48 cw(c568.7,2794.82) 588.01,2794.82 cw(c607.33,2794.82) EXTHDR1.100@593.67,2808.48 ; EXTHDR1.100@588.01,2859.25 588.01,2793.88 v1(598.52,2783.37) ; v3(5035.67,4111.26) U8.R5@5055.35,4130.94 ; U8.R5@5047.85,4130.94 cw(c5029.75,4130.94) 5042.55,4118.14 cw(c5055.35,4105.34) U8.R5@5055.35,4123.44 ; U8.R5@5048.01,4130.94 cw(c5030.29,4130.94) 5042.82,4118.41 cw(c5055.35,4105.88) U8.R5@5055.35,4123.6 ; 5048.47,4124.06 cw(c5035.67,4136.87) 5035.67,4118.76 ccw(c5035.67,4136.87) 5048.47,4124.06 ; 5048.47,4124.06 ccw(c5061.28,4111.26) 5043.17,4111.26 cw(c5061.28,4111.26) 5048.47,4124.06
  MidLayer1 w4: v1(3015.19,2641.71) 3131.86,2758.37 3131.86,3025.04 3465.19,3358.37 3465.19,3778.02 3528.88,3841.71 3701.5,3841.71 3748.19,3888.39 3748.19,4141.37 3765.19,4158.37 3781.86,4175.04 3890.19,4175.04 3906.86,4158.37 3906.86,4075.04 3848.52,4016.71 3848.52,3958.37 3873.52,3933.37 4143.51,3933.37 4333.84,4123.71 4498.52,4123.71 4506.86,4132.04 4506.86,4133.37 4523.52,4150.04 4548.52,4150.04 4556.86,4141.71 4556.86,4124.04 4565.19,4115.71 4633.47,4115.71 4637.47,4111.71 4695.77,4111.71 4703.98,4119.92 4738.62,4119.92 4745.99,4112.54 4758.64,4112.54 4762.8,4108.37 4815.8,4108.37 4828.42,4095.75 4860,4095.75 4870,4095.75 4918.62,4095.75 5012.16,4095.75 ccw(c5012.16,4109.8) 5022.09,4099.87 ; v1@3015.19,2647.21 ccw(c3015.19,2660.49) 3024.58,2651.1 ccw(c3033.97,2641.71) v1@3020.69,2641.71 ; v1@3015.19,2651.21 ccw(c3015.19,2674.14) 3031.41,2657.93 ccw(c3047.63,2641.71) v1@3024.69,2641.71 ; v3@5028.2,4111.91 cw(c5010.16,4113.49) 5021.8,4099.62 cw(c5033.44,4085.75) v3@5035.02,4103.79
  MidLayer2 w4: v1@598.52,2773.87 cw(c598.52,2750.94) 614.74,2767.16 cw(c630.96,2783.37) v1@608.02,2783.37 ; v1@598.52,2777.87 cw(c598.52,2764.6) 607.91,2773.99 cw(c617.3,2783.37) v1@604.02,2783.37 ; v1(598.52,2783.37) 623.52,2758.37 715.19,2758.37 723.52,2766.71 v1(797.52,2766.71) ; v1@790.81,2759.99 ccw(c774.59,2743.77) 774.59,2766.71 ccw(c774.59,2789.64) v1@790.81,2773.43 ; v1@793.64,2762.82 ccw(c784.25,2753.43) 784.25,2766.71 ccw(c784.25,2779.99) v1@793.64,2770.6
  Bottom Layer w4: v1(797.52,2766.71) 1056.86,2766.71 1065.19,2758.37 1092.92,2758.37 1125.92,2725.37 1523.54,2725.37 1565.21,2683.71 2168,2683.71 2210,2641.71 v1(3015.19,2641.71) ; v1@801.41,2762.82 cw(c810.8,2753.43) 810.8,2766.71 cw(c810.8,2779.99) v1@801.41,2770.6 ; v1@804.24,2759.99 cw(c820.46,2743.77) 820.46,2766.71 cw(c820.46,2789.64) v1@804.24,2773.43 ; v1@3008.47,2634.99 ccw(c2992.26,2618.77) 2992.26,2641.71 ccw(c2992.26,2664.64) v1@3008.47,2648.43 ; v1@3011.3,2637.82 ccw(c3001.91,2628.43) 3001.91,2641.71 ccw(c3001.91,2654.99) v1@3011.3,2645.6
PORT1.DMINUS: J36.2 U61.18 U62.6 | length 3743.6
  Top Layer w8: J36.2@5187.19,520.56 5176.93,566.04 ; J36.2@5195.02,523.07 5176.93,566.04 ; J36.2@5202.17,526.84 5176.93,566.04 ; J36.2@5209.9,533.07 5176.93,566.04 ; J36.2@5216.12,540.79 5176.93,566.04 ; J36.2@5219.9,547.94 5176.93,566.04 ; J36.2@5222.41,555.77 5176.93,566.04 ; 5435,841.82 5435,880 ; U61.18@5904.65,2240 5904.65,2215.35 5913,2207 5913,2193 5408.3,2193 5326.5,2111.2 5326.5,1223.34 5435,1114.84 5435,880 ; 5176.93,566.04 5176.93,593.07 5155,615 5155,710 5235,790 5400,790 5435,825 5435,880
  Bottom Layer w8: J36.2@5187.19,520.56 5176.93,566.04 ; J36.2@5195.02,523.07 5176.93,566.04 ; J36.2@5202.17,526.84 5176.93,566.04 ; J36.2@5209.9,533.07 5176.93,566.04 ; J36.2@5216.12,540.79 5176.93,566.04 ; J36.2@5219.9,547.94 5176.93,566.04 ; J36.2@5222.41,555.77 5176.93,566.04 ; U62.6@5297.76,972.4 5337.6,972.4 5340,970 5340,895 5155,710 5155,615 5176.93,593.07 5176.93,566.04 ; U62.6@5310.58,965.49 cw(c5327.27,948.79) 5327.27,972.4 cw(c5327.27,996.01) U62.6@5310.58,979.32
PORT1.DPLUS: J36.3 U61.20 U62.1 | length 3513.4
  Top Layer w8: J36.3@5200.22,587.76 5175.16,611.81 ; J36.3@5200.22,635.86 5175.16,611.81 ; J36.3@5205.27,594.5 5175.16,611.81 ; J36.3@5205.27,629.13 5175.16,611.81 ; J36.3@5208.48,601.99 5175.16,611.81 ; J36.3@5208.48,621.63 5175.16,611.81 ; U61.20@5944.01,2240 5944.01,2215.35 5933.33,2204.67 5933.33,2185 5929.33,2181 5413.27,2181 5338.5,2106.23 5338.5,1228.31 5447,1119.81 5447,820.03 5404.97,778 5239.97,778 5167,705.03 5167,619.97 5175.16,611.81 ; 5175.16,611.81 J36.3@5209.9,611.81 5175.16,611.81
  Bottom Layer w8: J36.3@5200.22,587.76 5175.16,611.81 ; J36.3@5200.22,635.86 5175.16,611.81 ; J36.3@5205.27,594.5 5175.16,611.81 ; J36.3@5205.27,629.13 5175.16,611.81 ; J36.3@5208.48,601.99 5175.16,611.81 ; J36.3@5208.48,621.63 5175.16,611.81 ; U62.1@5379.42,965.49 ccw(c5362.73,948.79) 5362.73,972.4 ccw(c5362.73,996.01) U62.1@5379.42,979.32 ; U62.1@5392.24,972.4 5356.4,972.4 5352,968 5352,890.03 5167,705.03 5167,619.97 5175.16,611.81 ; 5175.16,611.81 J36.3@5209.9,611.81 5175.16,611.81
PORT1.VBUS: F2.1 J36.1 J37.1 J38.1 R261.2 R262.2 R263.2 | length 8017.3
  MidLayer1 w4: v1(5081.86,2094.37) 5160.63,2094.37 5168.4,2086.6 5168.4,1888.47 5075,1795.06 5075,1760 5115.86,1719.14 5115.86,1396.39 5273.42,1238.83 5273.42,1098.42 5260,1085 5140,1085 v1(5115,1060) ; v1@5085.75,2090.49 cw(c5095.14,2081.1) 5095.14,2094.37 cw(c5095.14,2107.65) v1@5085.75,2098.26 ; v1@5088.57,2087.66 cw(c5104.79,2071.44) 5104.79,2094.37 cw(c5104.79,2117.31) v1@5088.57,2101.09 ; v1@5115,1065.5 ccw(c5115,1078.78) 5124.39,1069.39 ccw(c5133.78,1060) v1@5120.5,1060 ; v1@5115,1069.5 ccw(c5115,1092.43) 5131.22,1076.22 ccw(c5147.43,1060) v1@5124.5,1060
  MidLayer2 w4: v1(5115,1060) 5130.37,1075.37 5264.25,1075.37 5274.19,1065.43 5274.19,864.19 5260,850 5065,850 5038,823 5038,523 5061,500 5115,500 5160.67,454.33 ; J36.1@5185.93,440 ccw(c5160.67,424.9) 5160.67,454.33 ; J36.1@5185.93,468.66 cw(c5160.67,483.76) 5160.67,454.33 ; J36.1@5189.36,442.06 ccw(c5167.72,429.12) 5167.72,454.33 ccw(c5167.72,479.54) J36.1@5189.36,466.61 ; J36.1@5192.8,444.11 ccw(c5174.78,433.33) 5174.78,454.33 ccw(c5174.78,475.33) J36.1@5192.8,464.55 ; J36.1@5209.9,454.33 5160.67,454.33
  Bottom Layer w4: R263.2@5012.23,2152.92 cw(c4996.32,2137.01) 5018.82,2137.01 cw(c5041.32,2137.01) R263.2@5025.41,2152.92 ; R263.2@5012.23,2167.08 ccw(c4996.32,2182.99) 5018.82,2182.99 ccw(c5041.32,2182.99) R263.2@5025.41,2167.08 ; R262.2@5012.23,2208.83 cw(c4996.32,2192.92) 5018.82,2192.92 cw(c5041.32,2192.92) R262.2@5025.41,2208.83 ; R262.2@5012.23,2222.99 ccw(c4996.32,2238.9) 5018.82,2238.9 ccw(c5041.32,2238.9) R262.2@5025.41,2222.99 ; R261.2@5012.23,2264.74 cw(c4996.32,2248.83) 5018.82,2248.83 cw(c5041.32,2248.83) R261.2@5025.41,2264.74 ; R263.2@5015.06,2155.75 cw(c5005.98,2146.67) 5018.82,2146.67 cw(c5031.66,2146.67) R263.2@5022.58,2155.75 ; R263.2@5015.06,2164.25 ccw(c5005.98,2173.33) 5018.82,2173.33 ccw(c5031.66,2173.33) R263.2@5022.58,2164.25 ; R262.2@5015.06,2211.66 cw(c5005.98,2202.58) 5018.82,2202.58 cw(c5031.66,2202.58) R262.2@5022.58,2211.66 ; R262.2@5015.06,2220.16 ccw(c5005.98,2229.24) 5018.82,2229.24 ccw(c5031.66,2229.24) R262.2@5022.58,2220.16 ; R261.2@5015.06,2267.56 cw(c5005.98,2258.48) 5018.82,2258.48 cw(c5031.66,2258.48) R261.2@5022.58,2267.56 ; R261.2@5018.82,2271.82 R262.2@5018.82,2215.91 R263.2@5018.82,2160 5018.82,2121.18 5045.63,2094.37 v1(5081.86,2094.37) ; v1@5075.14,2087.66 ccw(c5058.92,2071.44) 5058.92,2094.37 ccw(c5058.92,2117.31) v1@5075.14,2101.09 ; v1@5077.97,2090.49 ccw(c5068.58,2081.1) 5068.58,2094.37 ccw(c5068.58,2107.65) v1@5077.97,2098.26
  Bottom Layer w20: F2.1@2531.46,1123.58 2658.32,1123.58 2690.19,1091.71 2690.19,775.04 2831.86,633.37 3716.63,633.37 4003.19,346.81 4688.19,346.81 4723.81,311.19 5086.19,311.19 5136,361 5176,361 5209.9,394.9 ; F2.1@2556.4,1098.63 cw(c2616.62,1038.41) 2616.62,1123.58 cw(c2616.62,1208.74) F2.1@2556.4,1148.52 ; J36.1@5195.81,440.24 cw(c5161.8,406.24) 5209.9,406.24 cw(c5257.99,406.24) J36.1@5223.98,440.24 ; J36.1@5209.9,454.33 5209.9,394.9 ; J37.1@5510.1,452.52 5529.9,364.8 J37.1@5549.69,452.52 ; J37.1@5529.9,454.72 5529.9,344.9 5501.04,316.04 5288.75,316.04 5209.9,394.9 ; 5530,343.58 5752.77,343.58 5784.19,375 5835,375 5849.9,389.9 ; J38.1@5830.21,451.25 5849.9,389.9 ; J38.1@5849.9,454.33 5849.9,389.9 ; J38.1@5869.58,451.25 5849.9,389.9
PORT2.DMINUS: J37.2 U61.25 U63.6 | length 3563.7
  Top Layer w8: J37.2@5507.19,520.95 5496.93,566.43 ; J37.2@5515.02,523.46 5496.93,566.43 ; J37.2@5522.17,527.24 5496.93,566.43 ; J37.2@5529.9,533.46 5496.93,566.43 ; J37.2@5536.12,541.19 5496.93,566.43 ; J37.2@5539.9,548.34 5496.93,566.43 ; J37.2@5542.41,556.17 5496.93,566.43 ; U61.25@6042.44,2240 6042.44,2215.35 6053.12,2204.67 6053.12,2190 6023.12,2160 5421.97,2160 5359.5,2097.53 5359.5,1237.01 5468,1128.51 5468,737 5475,730 5475,615.39 5496.93,593.47 5496.93,566.43
  Bottom Layer w8: J37.2@5507.19,520.95 5496.93,566.43 ; J37.2@5515.02,523.46 5496.93,566.43 ; J37.2@5522.17,527.24 5496.93,566.43 ; J37.2@5529.9,533.46 5496.93,566.43 ; J37.2@5536.12,541.19 5496.93,566.43 ; J37.2@5539.9,548.34 5496.93,566.43 ; J37.2@5542.41,556.17 5496.93,566.43 ; U63.6@5547.76,972.4 5583.6,972.4 5588,968 5588,843 5475,730 5475,615.39 5496.93,593.47 5496.93,566.43 ; U63.6@5560.58,965.49 cw(c5577.27,948.79) 5577.27,972.4 cw(c5577.27,996.01) U63.6@5560.58,979.32
PORT2.DPLUS: J37.3 U61.27 U63.1 | length 3366.5
  Top Layer w8: J37.3@5520.22,588.16 5495.16,612.2 ; J37.3@5520.22,636.25 5495.16,612.2 ; J37.3@5525.27,594.89 5495.16,612.2 ; J37.3@5525.27,629.52 5495.16,612.2 ; J37.3@5528.48,602.39 5495.16,612.2 ; J37.3@5528.48,622.02 5495.16,612.2 ; U61.27@6081.81,2240 6081.81,2215.35 6071.12,2204.67 6071.12,2191.03 6028.1,2148 5426.94,2148 5371.5,2092.56 5371.5,1241.98 5480,1133.48 5480,741.97 5487,734.97 5487,620.36 5495.16,612.2 ; 5495.16,612.2 J37.3@5529.9,612.2 5495.16,612.2
  Bottom Layer w8: J37.3@5520.22,588.16 5495.16,612.2 ; J37.3@5520.22,636.25 5495.16,612.2 ; J37.3@5525.27,594.89 5495.16,612.2 ; J37.3@5525.27,629.52 5495.16,612.2 ; J37.3@5528.48,602.39 5495.16,612.2 ; J37.3@5528.48,622.02 5495.16,612.2 ; U63.1@5629.42,965.49 ccw(c5612.73,948.79) 5612.73,972.4 ccw(c5612.73,996.01) U63.1@5629.42,979.32 ; U63.1@5642.24,972.4 5607.4,972.4 5600,965 5600,838.03 5487,725.03 5487,620.36 5495.16,612.2 ; 5495.16,612.2 J37.3@5529.9,612.2 5495.16,612.2
PORT3.DMINUS: J38.2 U61.32 U64.6 | length 3903.1
  Top Layer w8: J38.2@5827.19,520.56 5816.93,566.04 ; J38.2@5835.02,523.07 5816.93,566.04 ; J38.2@5842.17,526.84 5816.93,566.04 ; J38.2@5849.9,533.07 5816.93,566.04 ; J38.2@5856.12,540.79 5816.93,566.04 ; J38.2@5859.9,547.94 5816.93,566.04 ; J38.2@5862.41,555.77 5816.93,566.04 ; U61.32@6180.24,2240 6180.24,2215.35 6190.92,2204.67 6190.92,2189.67 6128.25,2127 5435.64,2127 5392.5,2083.86 5392.5,1250.68 5501,1142.18 5501,794 5515,780 5775,780 5795,760 5795,615 5816.93,593.07 5816.93,566.04
  Bottom Layer w8: U64.6@5797.76,972.4 5832.6,972.4 5838,967 5838,805.03 5795,762.03 5795,615 5816.93,593.07 5816.93,566.04 ; U64.6@5810.58,965.49 cw(c5827.27,948.79) 5827.27,972.4 cw(c5827.27,996.01) U64.6@5810.58,979.32 ; J38.2@5827.19,520.56 5816.93,566.04 ; J38.2@5835.02,523.07 5816.93,566.04 ; J38.2@5842.17,526.84 5816.93,566.04 ; J38.2@5849.9,533.07 5816.93,566.04 ; J38.2@5856.12,540.79 5816.93,566.04 ; J38.2@5859.9,547.94 5816.93,566.04 ; J38.2@5862.41,555.77 5816.93,566.04
PORT3.DPLUS: J38.3 U61.34 U64.1 | length 3720
  Top Layer w8: J38.3@5840.22,587.76 5815.16,611.81 ; J38.3@5840.22,635.86 5815.16,611.81 ; J38.3@5845.27,594.5 5815.16,611.81 ; J38.3@5845.27,629.13 5815.16,611.81 ; J38.3@5848.48,601.99 5815.16,611.81 ; J38.3@5848.48,621.63 5815.16,611.81 ; U61.34@6219.6,2240 6219.6,2200.35 6134.25,2115 5440.61,2115 5404.5,2078.89 5404.5,1255.65 5513,1147.15 5513,798.97 5519.97,792 5780,792 5807,765 5807,619.97 5815.16,611.81 ; 5815.16,611.81 J38.3@5849.9,611.81 5815.16,611.81
  Bottom Layer w8: J38.3@5840.22,587.76 5815.16,611.81 ; J38.3@5840.22,635.86 5815.16,611.81 ; J38.3@5845.27,594.5 5815.16,611.81 ; J38.3@5845.27,629.13 5815.16,611.81 ; J38.3@5848.48,601.99 5815.16,611.81 ; J38.3@5848.48,621.63 5815.16,611.81 ; 5850,810 5850,820 ; U64.1@5879.42,965.49 ccw(c5862.73,948.79) 5862.73,972.4 ccw(c5862.73,996.01) U64.1@5879.42,979.32 ; U64.1@5892.24,972.4 5852.4,972.4 5850,970 5850,820 ; 5815.16,611.81 J38.3@5849.9,611.81 5815.16,611.81 ; 5815.16,611.81 5807,619.97 5807,757.06 5850,800.06 5850,820
PROG_B: R74.2 U8.A2 | length 11007.1
  Top Layer w4: v1(4490.19,5533.37) 4587.21,5533.37 4631.86,5488.73 4631.86,5126.04 4665.19,5092.71 4665.19,4913.02 4736.5,4841.71 4833.19,4841.71 4863.86,4811.04 4863.86,4797.39 4904.25,4757 4928,4757 4937.24,4747.76 4937.24,4720 4937.24,4710 U8.A2@4937.24,4682.13 ; v1@4494.08,5529.49 cw(c4503.47,5520.1) 4503.47,5533.37 cw(c4503.47,5546.65) v1@4494.08,5537.26 ; v1@4496.91,5526.66 cw(c4513.13,5510.44) 4513.13,5533.37 cw(c4513.13,5556.31) v1@4496.91,5540.09 ; U8.A2@4931.94,4687.43 ccw(c4919.14,4700.23) 4937.24,4700.23 ccw(c4955.35,4700.23) U8.A2@4942.55,4687.43 ; U8.A2@4932.05,4687.32 ccw(c4919.52,4699.85) 4937.24,4699.85 ccw(c4954.97,4699.85) U8.A2@4942.44,4687.32
  MidLayer2 w4: v1(4490.19,5533.37) 4598.52,5641.71 4755,5641.71 4830,5716.71 5312.21,5716.71 5337.21,5691.71 6614.6,5691.71 6797.27,5509.04 7105.96,5509.04 7145,5470 7255,5470 7267,5458 7267,5333 7495,5105 7807.25,5105 8106.86,4805.39 8106.86,4735 ; v1@4490.19,5538.87 ccw(c4490.19,5552.15) 4499.58,5542.76 ccw(c4508.97,5533.37) v1@4495.69,5533.37 ; v1@4490.19,5542.87 ccw(c4490.19,5565.81) 4506.41,5549.59 ccw(c4522.63,5533.37) v1@4499.69,5533.37 ; v1(7223.52,3325.04) 7315.19,3416.71 7323.86,3425.37 7323.86,3545.23 7345,3566.37 7706.52,3566.37 7965.19,3825.04 7965.19,3864.06 8065.19,3964.06 8065.19,3995.28 8106.86,4036.94 8106.86,4735 ; v1@7223.52,3330.54 ccw(c7223.52,3343.82) 7232.91,3334.43 ccw(c7242.3,3325.04) v1@7229.02,3325.04 ; v1@7223.52,3334.54 ccw(c7223.52,3357.48) 7239.74,3341.26 ccw(c7255.96,3325.04) v1@7233.02,3325.04 ; 8106.86,4755 8106.86,4735
  Bottom Layer w4: R74.2@5699.23,2707.92 cw(c5683.32,2692.01) 5705.82,2692.01 cw(c5728.32,2692.01) R74.2@5712.41,2707.92 ; R74.2@5702.06,2710.75 cw(c5692.98,2701.67) 5705.82,2701.67 cw(c5718.66,2701.67) R74.2@5709.58,2710.75 ; R74.2@5705.82,2715 5705.82,2608.37 5722.49,2591.71 5776.88,2591.71 5807.21,2561.37 6203.86,2561.37 6250.19,2515.04 6552.21,2515.04 6595.54,2558.37 6922.88,2558.37 6972.88,2608.37 7123.52,2608.37 7340.19,2825.04 7673.52,2825.04 7848.52,3000.04 7848.52,3033.37 7831.86,3050.04 7794.96,3050.04 7770,3075 7600,3075 7553.63,3121.37 7402.19,3121.37 7223.52,3300.04 v1(7223.52,3325.04) ; v1@7216.81,3318.32 cw(c7200.59,3302.11) 7223.52,3302.11 cw(c7246.46,3302.11) v1@7230.24,3318.32 ; v1@7219.64,3321.15 cw(c7210.25,3311.76) 7223.52,3311.76 cw(c7236.8,3311.76) v1@7227.41,3321.15
PWFBIN: C42.2 L1.2 U5.8 | length 1353.8
  MidLayer2 w12: v4(2320,5410) 2443.88,5410 2454.42,5420.54 2820,5420.54 3005.54,5235 v4(3140,5235) ; v4@2324.11,5405.89 cw(c2334.03,5395.97) 2334.03,5410 cw(c2334.03,5424.03) v4@2324.11,5414.11 ; v4@3135.89,5230.89 ccw(c3125.97,5220.97) 3125.97,5235 ccw(c3125.97,5249.03) v4@3135.89,5239.11
  Bottom Layer w12: v4@2315.89,5405.89 cw(c2305.97,5395.97) 2320,5395.97 cw(c2334.03,5395.97) v4@2324.11,5405.89 ; v4(2320,5410) 2320,5365 2331.34,5353.66 U5.8@2331.34,5322.68 ; 2326.07,5358.93 cw(c2313.34,5346.2) U5.8@2331.34,5346.2 ; L1.2@3115.32,5185.62 ccw(c3091.96,5208.98) 3125,5208.98 ccw(c3158.04,5208.98) L1.2@3134.68,5185.62 ; v4(3140,5235) 3125,5220 L1.2@3125,5175.94 3145.67,5155.28 C42.2@3145.67,5120 ; C42.2@3141.56,5124.11 ccw(c3131.64,5134.03) 3145.67,5134.03 ccw(c3159.7,5134.03) C42.2@3149.78,5124.11 ; C42.2@3145.67,5121.52 cw(c3208.95,5121.52) L1.2@3164.2,5166.27 ; 3145.67,5150.49 cw(c3179.98,5150.49) L1.2@3155.72,5174.75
